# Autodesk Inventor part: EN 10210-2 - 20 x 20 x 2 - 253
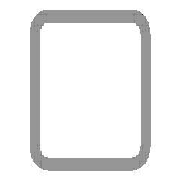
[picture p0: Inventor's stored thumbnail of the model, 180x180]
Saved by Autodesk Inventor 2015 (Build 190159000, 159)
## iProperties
Created: 2015-05
Part Number: EN 10210-2 - 20 x 20 x 2 - 253
Material: Steel, Mild
Description: Tube
Document SubType Name: Modeling
Standard: DIN
Designer: TREINA6
Standard Revision: 1997
Standards Organization: DIN
Language: en-US
Size Designation: 20 x 20 x 2
Categories: <MemberInstance><Categories><Category DisplayName="Structural Shapes" InternalName="089c4875-fa83-4c05-b084-43b9cc11f5ed" Mnemonic="GRDR"><CategoryParameter Dis
Stock Number: 20 x 20 x 2
Density: 7.85 g/cm^3
Appearance: Semi-Polished
_CCFamilyMember: 1
_CCFamilyDisplayName: DIN EN 10210-2 (Square) - Tube
_FrameMemberDoc: Frame Member File
_Version: 15.0.0
_GetPNFromCC: 1
IsCustomPart: 1
Author: TREINA6
G_L: 253,000 mm
G_W: 20,000 mm
G_H: 20,000 mm
+9A0701DD-5C28-48D1-9548-9F52B9A0137C+CUTDETAIL1: Miter 45,00 deg
+1C2C2078-6D63-4675-889F-DB36AB8CDDC0+CUTDETAIL2: Miter 45,00 deg
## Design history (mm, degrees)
node "Start plane"
node "End plane"
sketch "Sketch"
  geometry: L1 (-10, -7)-(-10, 7); L2 (-7, 10)-(7, 10); L3 (10, 7)-(10, -7); L4 (7, -10)-(-7, -10); L5 (-7, 8)-(7, 8); L6 (8, 7)-(8, -7); L7 (7, -8)-(-7, -8); L8 (-8, -7)-(-8, 7); L9 (0, 14.87)-(0, -14.87) reference; L10 (-14.87, 0)-(14.87, 0) reference; A1 r 3 centre (-7, -7) between (-10, -7) and (-7, -10); A2 r 3 centre (-7, 7) between (-7, 10) and (-10, 7); A3 r 3 centre (7, 7) between (10, 7) and (7, 10); A4 r 3 centre (7, -7) between (7, -10) and (10, -7); A5 r 1 centre (-7, 7) between (-7, 8) and (-8, 7); A6 r 1 centre (7, 7) between (8, 7) and (7, 8); A7 r 1 centre (7, -7) between (7, -8) and (8, -7); A8 r 1 centre (-7, -7) between (-8, -7) and (-7, -8)
  constraints: 16 end point, 16 point on circle, 8 centre point, 8 tangent, 4 parallel, 3 equal radius, 2 perpendicular, 7 other
  dimensions: "d7" = 3 radius of A1 (= G_IR); "d10" = 20 distance between parallel lines of L2 L4 (= G_H); "d11" = 20 distance between parallel lines of L1 L3 (= G_W); "d12" = 2 distance between parallel lines of L3 L6 (= G_T); "d15" = 10 distance between parallel lines of L2 L10 (= 0.5 x d10); "d16" = 10 distance between parallel lines of L9 L3 (= 0.5 x d11)
extrude "Body" new body sketch "Sketch" stored distance "d3" = 253 (= G_L); taper "d4" = 0 deg
node "Driven Length"
  sketch "Sketch3"
    geometry: L1 (0, 0)-(10, 0) reference
    constraints: 2 end point, 1 horizontal
  workplane "Work Plane3"
  sketch "Sketch4"
    geometry: L1 (-2, 0)-(12, 0) reference; L2 (-2, 253)-(12, 253) reference
    dimensions: "d18" = 253 distance between parallel lines of L1 L2 (derived)
workplane "Work Plane4"
split "Split1"
workplane "Work Plane5"
split "Split2"
body "Solid1"
other parameters: "G_W" = 20 [user parameter; used in 1 equation term], "G_H" = 20 [user parameter; used in 1 equation term], "G_T" = 2 [user parameter; used in 1 equation term], "G_IR" = 3 [user parameter; used in 1 equation term], "G_L" = 253 (= d18) [user parameter; used in 1 equation term], "G_OFFSET_START" = 0 [user parameter; used in 1 equation term], "G_OFFSET_END" = 0 [user parameter; used in 1 equation term], "d13" = 0 (computed from G_OFFSET_START), "d14" = 253 (= G_OFFSET_END + B_L), "B_L" = 253 [user parameter; used in 1 equation term], "d17" = 90 deg
